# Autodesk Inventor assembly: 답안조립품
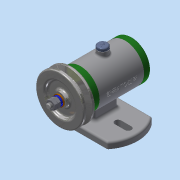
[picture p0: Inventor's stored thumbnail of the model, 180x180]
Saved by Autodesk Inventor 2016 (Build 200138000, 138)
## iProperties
Created: 2017-12
Part Number: 답안조립품
Material: 일반
Document SubType Name: Assembly
Designer: 605-15
Author: 605-15
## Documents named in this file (14)
- C:\Users\605-15\Desktop\471207V1006\답안조립품.iam
- C:\Users\605-15\Desktop\471207V1006\본체.ipt
- C:\Users\605-15\Desktop\471207V1006\축.ipt
- C:\Users\605-15\Desktop\471207V1006\베어링 15 x 32 x 9.ipt
- C:\Users\605-15\Desktop\471207V1006\뒤커버.ipt
- C:\Users\605-15\Desktop\471207V1006\앞커버.ipt
- C:\Users\605-15\Desktop\471207V1006\오일 실 15 25 7.ipt
- C:\Users\605-15\Desktop\471207V1006\볼트 M4 x 12.ipt
- C:\Users\605-15\Desktop\471207V1006\고무캡.ipt
- C:\Users\605-15\Desktop\471207V1006\V벨트풀리.ipt
- C:\Users\605-15\Desktop\471207V1006\키 3 x 3 x 12.ipt
- C:\Users\605-15\Desktop\471207V1006\와셔 8x17.ipt
- C:\Users\605-15\Desktop\471207V1006\스프링와셔 8.ipt
- C:\Users\605-15\Desktop\471207V1006\너트 M 8.ipt
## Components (2 placed, 2 different names)
1. 고무캡:1
2. V벨트풀리:1 — 각도:2
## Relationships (1: Angle 1)
- 각도:2 [Angle]: V벨트풀리:1
